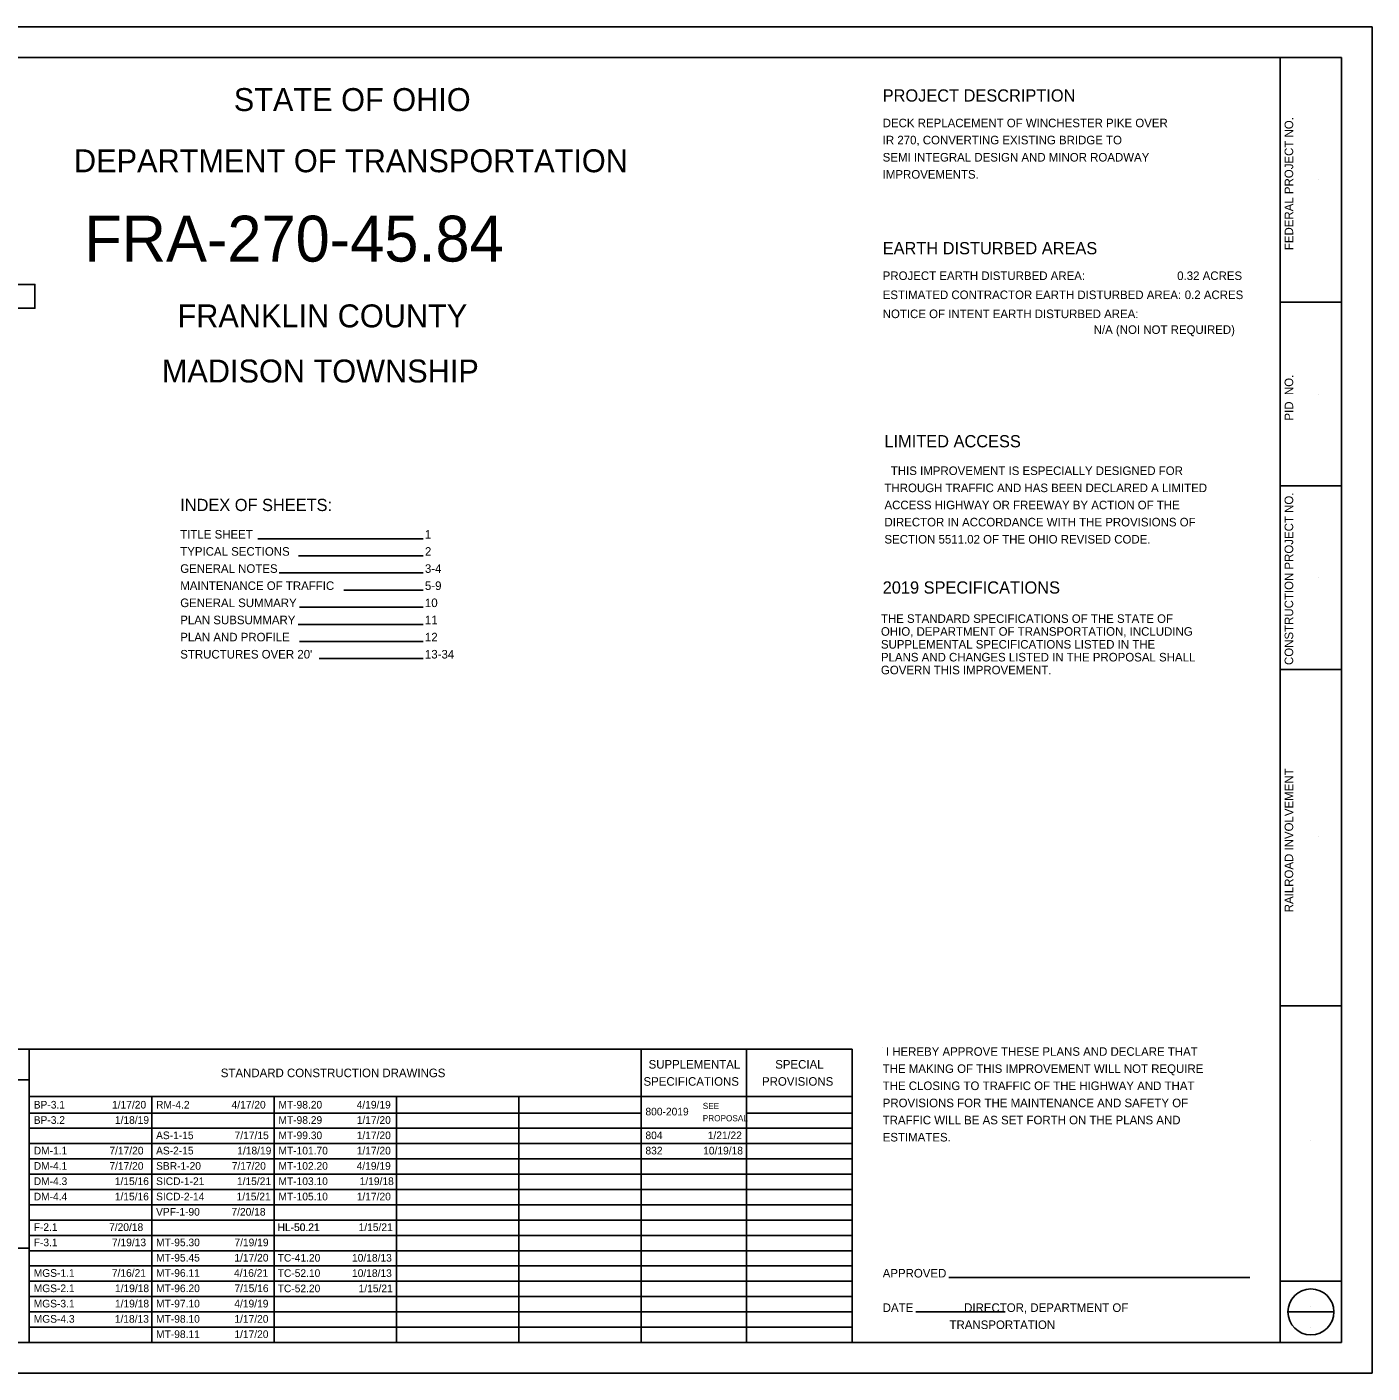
# Model space of a CAD drawing. Extents: x 0 to 34, y 0 to 22.
# Drawn here: x 12.01 to 34, y 0 to 22 of the extents above; entities that cross this region are included whole.
import ezdxf

# ---------------------------------------------------------------- set-up
doc = ezdxf.new("R2010")
doc.units = 0
for name, color, linetype in [('BD_P_Text', 7, 'Continuous'), ('SH_Border', 7, 'Continuous'), ('SH_Cut_Line', 7, 'Continuous'), ('SH_Data', 7, 'Continuous')]:
    doc.layers.add(name, color=color, linetype=linetype)

msp = doc.modelspace()

# ---------------------------------------------------------------- linework, layer by layer
at = {"layer": 'BD_P_Text'}
msp.add_lwpolyline([(9.749, 17.793), (12.142, 17.793), (12.142, 17.401), (9.749, 17.401)], close=True, dxfattribs=at)
at = {"layer": 'SH_Border'}
for p, q in [((32.5, 0.5), (32.5, 21.5)), ((32.5, 17.5), (33.5, 17.5)), ((32.5, 14.5), (33.5, 14.5)), ((32.5, 11.5), (33.5, 11.5)), ((32.5, 6), (33.5, 6)), ((32.5, 1.5), (33.5, 1.5))]:
    msp.add_line(p, q, dxfattribs=at)
msp.add_lwpolyline([(2, 21.5), (33.5, 21.5), (33.5, 0.5), (2, 0.5)], close=True, dxfattribs=at)
at = {"layer": 'SH_Cut_Line'}
msp.add_lwpolyline([(0, 0), (34, 0), (34, 22), (0, 22)], close=True, dxfattribs=at)
at = {"layer": 'SH_Data'}
for p, q in [((33.125, 19.5), (33.125, 19.5)), ((33.125, 16), (33.125, 16)), ((15.788, 13.636), (18.487, 13.636)), ((16.45, 13.356), (18.487, 13.356)), ((16.136, 13.076), (18.487, 13.076)), ((33.125, 13), (33.125, 13)), ((17.192, 12.796), (18.487, 12.796)), ((16.464, 12.516), (18.487, 12.516)), ((16.444, 12.236), (18.487, 12.236)), ((16.468, 11.956), (18.487, 11.956)), ((16.786, 11.676), (18.487, 11.676)), ((33.125, 8.766), (33.125, 8.766)), ((9.25, 5.292), (12.05, 5.292)), ((12.05, 5.292), (25.5, 5.292)), ((12.05, 0.5), (12.05, 5.292)), ((22.05, 0.5), (22.05, 5.292)), ((23.775, 0.5), (23.775, 5.292)), ((25.5, 0.5), (25.5, 5.292)), ((26, 5.325), (26, 5.325)), ((9.25, 4.792), (12.05, 4.792)), ((12.05, 4.521), (25.5, 4.521)), ((14.05, 0.5), (14.05, 4.521)), ((16.05, 0.5), (16.05, 4.521)), ((18.05, 0.5), (18.05, 4.521)), ((20.05, 0.5), (20.05, 4.521)), ((12.05, 4.25), (22.05, 4.25)), ((23.775, 4.25), (25.5, 4.25)), ((12.05, 4), (25.5, 4)), ((12.05, 3.75), (25.5, 3.75)), ((33, 3.799), (33, 3.799)), ((12.05, 3.5), (25.5, 3.5)), ((12.05, 3.25), (25.5, 3.25)), ((12.05, 3), (25.5, 3)), ((12.05, 2.75), (25.5, 2.75)), ((12.05, 2.5), (25.5, 2.5)), ((12.05, 2.25), (25.5, 2.25)), ((9.25, 2.042), (12.05, 2.042)), ((12.05, 2), (25.5, 2)), ((12.05, 1.75), (25.5, 1.75)), ((27.08, 1.562), (32, 1.562)), ((12.05, 1.5), (25.5, 1.5)), ((12.05, 1.25), (25.5, 1.25)), ((12.05, 1), (25.5, 1)), ((26.542, 0.999), (28, 0.999)), ((32.625, 1), (33.375, 1)), ((33, 1.085), (33, 1.085)), ((12.05, 0.75), (25.5, 0.75)), ((33, 0.745), (33, 0.745))]:
    msp.add_line(p, q, dxfattribs=at)
msp.add_circle((33, 1), 0.375, dxfattribs=at)

# ---------------------------------------------------------------- texts
at = {"layer": 'BD_P_Text'}
for s, p in [(' I HEREBY APPROVE THESE PLANS AND DECLARE THAT', (26, 5.185)), ('THE MAKING OF THIS IMPROVEMENT WILL NOT REQUIRE', (26, 4.905)), ('THE CLOSING TO TRAFFIC OF THE HIGHWAY AND THAT', (26, 4.625)), ('PROVISIONS FOR THE MAINTENANCE AND SAFETY OF', (26, 4.345)), ('TRAFFIC WILL BE AS SET FORTH ON THE PLANS AND', (26, 4.065)), ('ESTIMATES.', (26, 3.785))]:
    msp.add_text(s, height=0.14, dxfattribs=at).set_placement(p)
at = {"layer": 'SH_Data'}
for s, height, p in [('STATE OF OHIO', 0.375, (15.392, 20.625)), ('PROJECT DESCRIPTION', 0.2, (26, 20.78)), ('DECK REPLACEMENT OF WINCHESTER PIKE OVER', 0.14, (26, 20.36)), ('IR 270, CONVERTING EXISTING BRIDGE TO ', 0.14, (26, 20.081)), ('DEPARTMENT OF TRANSPORTATION', 0.375, (12.78, 19.625)), ('SEMI INTEGRAL DESIGN AND MINOR ROADWAY', 0.14, (26, 19.8)), ('IMPROVEMENTS.', 0.14, (26, 19.52)), ('FRA-270-45.84', 0.75, (12.948, 18.165)), ('EARTH DISTURBED AREAS', 0.2, (26, 18.284)), ('PROJECT EARTH DISTURBED AREA:', 0.14, (26, 17.864)), ('0.32 ACRES', 0.14, (30.814, 17.864)), ('ESTIMATED CONTRACTOR EARTH DISTURBED AREA:', 0.14, (26, 17.552)), ('0.2 ACRES', 0.14, (30.937, 17.552)), ('FRANKLIN COUNTY', 0.375, (14.472, 17.09)), ('NOTICE OF INTENT EARTH DISTURBED AREA:', 0.14, (26, 17.241)), ('N/A (NOI NOT REQUIRED)', 0.14, (29.449, 16.983)), ('MADISON TOWNSHIP', 0.375, (14.216, 16.189)), ('LIMITED ACCESS', 0.2, (26.029, 15.129)), ('  THIS IMPROVEMENT IS ESPECIALLY DESIGNED FOR', 0.14, (26.029, 14.677)), ('THROUGH TRAFFIC AND HAS BEEN DECLARED A LIMITED', 0.14, (26.029, 14.397)), ('INDEX OF SHEETS:', 0.2, (14.517, 14.088)), ('ACCESS HIGHWAY OR FREEWAY BY ACTION OF THE', 0.14, (26.029, 14.117)), ('DIRECTOR IN ACCORDANCE WITH THE PROVISIONS OF', 0.14, (26.029, 13.837)), ('TITLE SHEET', 0.14, (14.517, 13.638)), ('1', 0.14, (18.517, 13.638)), ('SECTION 5511.02 OF THE OHIO REVISED CODE.', 0.14, (26.029, 13.557)), ('TYPICAL SECTIONS', 0.14, (14.517, 13.358)), ('2', 0.14, (18.517, 13.358)), ('GENERAL NOTES', 0.14, (14.517, 13.078)), ('3-4', 0.14, (18.517, 13.078)), ('MAINTENANCE OF TRAFFIC', 0.14, (14.517, 12.798)), ('5-9', 0.14, (18.517, 12.798)), ('2019 SPECIFICATIONS', 0.2, (26, 12.739)), ('GENERAL SUMMARY', 0.14, (14.517, 12.518)), ('10', 0.14, (18.517, 12.518)), ('PLAN SUBSUMMARY', 0.14, (14.517, 12.238)), ('11', 0.14, (18.517, 12.238)), ('THE STANDARD SPECIFICATIONS OF THE STATE OF', 0.14, (25.971, 12.26)), ('OHIO, DEPARTMENT OF TRANSPORTATION, INCLUDING', 0.14, (25.971, 12.05)), ('PLAN AND PROFILE', 0.14, (14.517, 11.958)), ('12', 0.14, (18.517, 11.958)), ('SUPPLEMENTAL SPECIFICATIONS LISTED IN THE', 0.14, (25.971, 11.84)), ("STRUCTURES OVER 20'", 0.14, (14.517, 11.678)), ('13-34', 0.14, (18.517, 11.678)), ('PLANS AND CHANGES LISTED IN THE PROPOSAL SHALL', 0.14, (25.971, 11.63)), ('GOVERN THIS IMPROVEMENT.', 0.14, (25.971, 11.42)), ('SUPPLEMENTAL', 0.14, (22.173, 4.976)), ('SPECIAL', 0.14, (24.243, 4.976)), ('STANDARD CONSTRUCTION DRAWINGS', 0.14, (15.18, 4.836)), ('SPECIFICATIONS', 0.14, (22.09, 4.696)), ('PROVISIONS', 0.14, (24.027, 4.696)), ('BP-3.1', 0.125, (12.122, 4.323)), ('1/17/20', 0.125, (13.402, 4.323)), ('RM-4.2', 0.125, (14.122, 4.323)), ('4/17/20', 0.125, (15.356, 4.323)), ('MT-98.20', 0.125, (16.122, 4.323)), ('4/19/19', 0.125, (17.401, 4.323)), ('SEE', 0.1002, (23.059, 4.316)), ('BP-3.2', 0.125, (12.122, 4.073)), ('1/18/19', 0.125, (13.449, 4.073)), ('MT-98.29', 0.125, (16.122, 4.073)), ('1/17/20', 0.125, (17.402, 4.073)), ('800-2019', 0.125, (22.122, 4.211)), ('PROPOSAL', 0.1002, (23.059, 4.115)), ('AS-1-15', 0.125, (14.122, 3.823)), ('7/17/15', 0.125, (15.406, 3.823)), ('MT-99.30', 0.125, (16.122, 3.823)), ('1/17/20', 0.125, (17.402, 3.823)), ('804', 0.125, (22.122, 3.823)), ('1/21/22', 0.125, (23.14, 3.823)), ('DM-1.1', 0.125, (12.122, 3.573)), ('7/17/20', 0.125, (13.359, 3.573)), ('AS-2-15', 0.125, (14.122, 3.573)), ('1/18/19', 0.125, (15.449, 3.573)), ('MT-101.70', 0.125, (16.122, 3.573)), ('1/17/20', 0.125, (17.402, 3.573)), ('832', 0.125, (22.122, 3.573)), ('10/19/18', 0.125, (23.065, 3.573)), ('DM-4.1', 0.125, (12.122, 3.323)), ('7/17/20', 0.125, (13.359, 3.323)), ('SBR-1-20', 0.125, (14.122, 3.323)), ('7/17/20', 0.125, (15.359, 3.323)), ('MT-102.20', 0.125, (16.122, 3.323)), ('4/19/19', 0.125, (17.401, 3.323)), ('DM-4.3', 0.125, (12.122, 3.073)), ('1/15/16', 0.125, (13.447, 3.073)), ('SICD-1-21', 0.125, (14.122, 3.073)), ('1/15/21', 0.125, (15.444, 3.073)), ('MT-103.10', 0.125, (16.122, 3.073)), ('1/19/18', 0.125, (17.45, 3.073)), ('DM-4.4', 0.125, (12.122, 2.823)), ('1/15/16', 0.125, (13.447, 2.823)), ('SICD-2-14', 0.125, (14.122, 2.823)), ('1/15/21', 0.125, (15.438, 2.823)), ('MT-105.10', 0.125, (16.122, 2.823)), ('1/17/20', 0.125, (17.402, 2.823)), ('VPF-1-90', 0.125, (14.122, 2.573)), ('7/20/18', 0.125, (15.354, 2.573)), ('F-2.1', 0.125, (12.122, 2.323)), ('7/20/18', 0.125, (13.354, 2.323)), ('HL-50.21', 0.125, (16.106, 2.321)), ('HL-50.21', 0.125, (16.11, 2.321)), ('1/15/21', 0.125, (17.433, 2.321)), ('7/19/13', 0.125, (13.401, 2.073)), ('7/19/19', 0.125, (15.403, 2.073)), ('F-3.1', 0.125, (12.122, 2.073)), ('MT-95.30', 0.125, (14.122, 2.073)), ('MT-95.45', 0.125, (14.122, 1.823)), ('1/17/20', 0.125, (15.402, 1.823)), ('TC-41.20', 0.125, (16.11, 1.821)), ('10/18/13', 0.125, (17.325, 1.821)), ('MGS-1.1', 0.125, (12.122, 1.573)), ('7/16/21', 0.125, (13.399, 1.573)), ('MT-96.11', 0.125, (14.122, 1.573)), ('4/16/21', 0.125, (15.396, 1.573)), ('TC-52.10', 0.125, (16.11, 1.571)), ('10/18/13', 0.125, (17.325, 1.571)), ('APPROVED', 0.14, (26, 1.562)), ('MGS-2.1', 0.125, (12.122, 1.323)), ('1/19/18', 0.125, (13.45, 1.323)), ('MT-96.20', 0.125, (14.122, 1.323)), ('7/15/16', 0.125, (15.403, 1.323)), ('TC-52.20', 0.125, (16.11, 1.321)), ('1/15/21', 0.125, (17.433, 1.321)), ('MGS-3.1', 0.125, (12.122, 1.073)), ('1/19/18', 0.125, (13.45, 1.073)), ('MT-97.10', 0.125, (14.122, 1.073)), ('4/19/19', 0.125, (15.401, 1.073)), ('DATE                DIRECTOR, DEPARTMENT OF', 0.14, (26, 0.999)), ('MGS-4.3', 0.125, (12.122, 0.823)), ('1/18/13', 0.125, (13.447, 0.823)), ('MT-98.10', 0.125, (14.122, 0.823)), ('1/17/20', 0.125, (15.402, 0.823)), ('MT-98.11', 0.125, (14.122, 0.573)), ('1/17/20', 0.125, (15.402, 0.573)), ('                     TRANSPORTATION', 0.14, (26, 0.72))]:
    msp.add_text(s, height=height, dxfattribs=at).set_placement(p)
for s, p in [('FEDERAL PROJECT NO.', (32.71, 18.352)), ('PID  NO.', (32.71, 15.567)), ('CONSTRUCTION PROJECT NO.', (32.71, 11.572)), ('RAILROAD INVOLVEMENT', (32.71, 7.531))]:
    msp.add_text(s, height=0.14, rotation=90, dxfattribs=at).set_placement(p)

doc.saveas('drawing.dxf')
